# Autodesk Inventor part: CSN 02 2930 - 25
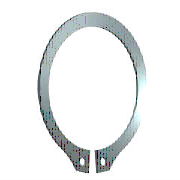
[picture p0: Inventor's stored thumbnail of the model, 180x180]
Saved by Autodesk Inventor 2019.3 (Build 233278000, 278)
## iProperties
Created: 2018-01
Part Number: CSN 02 2930 - 25
Material: Ocel, měkká
Description: Pojistné hřídelové kroužky. Rozměry
Document SubType Name: Modeling
Standard: CSN 02 2930
Designer: B-hon
Standards Organization: CSN
Language: cs-CZ
Size Designation: 25
Categories: <MemberInstance><Categories><Category DisplayName="Součásti hřídele" InternalName="7f7aeb1f-a693-4053-b835-cee3144e0d98" Mnemonic="SHFT"><Category DisplayName="
Density: 7.85 g/cm^3
Appearance: Pololeštěná
IsCustomPart: 0
Author: B-hon
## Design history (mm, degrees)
sketch "Náčrt1"
  geometry: L1 (-6, 0)-(6, 0) reference; L2 (0, 20.189)-(0, -80.536) reference; L3 (-48.09, 0)-(48.09, 0) reference; L4 (-0.5, -24.44)-(-0.5, -28.74); L5 (-0.5, -6.54)-(-0.5, -13.29); L6 (-2.795, 3.1)-(3.672, 3.1); L7 (0.5, -6.54)-(0.5, -13.29); L8 (0.5, -24.44)-(0.5, -28.74); C1 r 1 at (-2, -26.606); C2 r 1 at (2, -26.606); A1 r 11.95 centre (0, -12.5) between (0.5, -24.44) and (-0.5, -24.44); A2 r 14.825 centre (0, -11.725) between (5.202, -25.608) and (-5.202, -25.608); A3 r 16.247 centre (0, -12.5) between (-2.281, -28.586) and (-0.5, -28.74); A4 r 2 centre (-2, -26.606) between (-3.952, -27.043) and (-2.281, -28.586); A5 r 2 centre (-5.903, -27.48) between (-3.952, -27.043) and (-5.202, -25.608); A6 r 2 centre (5.903, -27.48) between (5.202, -25.608) and (3.952, -27.043); A7 r 2 centre (2, -26.606) between (2.281, -28.586) and (3.952, -27.043); A8 r 16.247 centre (0, -12.5) between (0.5, -28.74) and (2.281, -28.586)
  constraints: 16 point on circle, 12 end point, 10 centre point, 9 symmetric about line, 5 point on line, 4 tangent, 3 coincident, 2 horizontal, 1 perpendicular, 1 vertical, 5 other
  dimensions: "d0" = 23.9 diameter of A1 (= ND); "d1" = 4.3 distance of L4.end L4.start (= SRB2); "d6" = 0.5 distance between parallel lines of L2 L5 (= 0.25 x SD5); "d7" = 3.1 distance between parallel lines of L6 L3 (= SRB1); "d8" = 0.775 distance of A1.centre A2.centre (= 0.25 x SRB1); "d9" = 2 radius of A4 (= SD5); "d10" = 2 radius of A5 (= SD5); "d11" = 1.5 distance from line of L4 A4.centre (= 0.75 x SD5); "d12" = 2 diameter of C1 (= SD5); "d13" = 2 diameter of C2 (= SD5); "d14" = 12.5 distance from line of A1.centre L1 (= 0.5 x WD)
extrude "Těleso" new body sketch "Náčrt1" distance "d2" = 1.2 (= SD); taper "d3" = 0 deg
workaxis "Work Axis1"
workplane "Work Plane1"
body "Solid1"
other parameters: "WD" = 25 (= WDMIN) [user parameter; used in 1 equation term], "SD" = 1.2 [user parameter; used in 1 equation term], "SRB1" = 3.1 [user parameter; used in 2 equation terms], "ND" = 23.9 [user parameter; used in 1 equation term], "SRB2" = 4.3 [user parameter; used in 1 equation term], "SD5" = 2 [user parameter; used in 6 equation terms], "d15" = 0, "d16" = 0, "d17" = 0, "d41" = 0, "d42" = 0, "WDMIN" = 25 [user parameter; used in 1 equation term], "SD3" = 23.2 [user parameter], "WDMAX" = 26 [user parameter]
